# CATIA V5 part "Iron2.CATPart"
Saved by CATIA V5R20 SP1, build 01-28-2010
Part number: Part1
Bounding box of the stored display mesh (mm): x -79.132 to 79.133, y -300 to 0, z -3.105 to 127.728
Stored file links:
  J:\hosseini\Iron2.CATPart
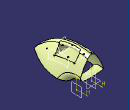
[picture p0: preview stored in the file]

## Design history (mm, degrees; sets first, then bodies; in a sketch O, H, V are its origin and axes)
Body1 (main body)
  Sketch1 on zx-plane, origin (0, 0, 0), H (-1, 0, 0), V (0, 0, 1)
    point P1 (70, 0)
    arc A1 centre (-241.0845, -75.0096) radius 320 from (70, 0) to (20.4309, 109.4076) ccw
    arc A2 centre (0, 95) radius 25 from (20.4309, 109.4076) to (-20.4309, 109.4076) ccw
    point P4 (0, 95)
    arc A3 centre (241.0845, -75.0096) radius 320 from (-20.4309, 109.4076) to (-70, 0) ccw
    point P7 (-70, 0)
    distance A2 H = 120
    distance P1 V = 70
    radius A2 = 25
    radius A1 = 320
    coincidence: P1 H, P7 H, P4 V
    tangency: A2 A1, A3 A2
    symmetry: A1 A3 V
  Sketch2 on yz-plane, origin (0, 0, 0), H (0, 1, 0), V (0, 0, 1)
    spline S1 through (0, 120) (-97.5385, 126.0039) (-300, 0)
    point P1 (0, 120)
    point P2 (-300, 0)
    distance P2 V = 300
    distance P1 H = 120
    coincidence: P1 V, P2 H
  Sketch3 on xy-plane, origin (0, 0, 0), H (1, 0, 0), V (0, 1, 0)
    spline S1 through (70, 0) (71.6167, -27.0715) (76.454, -63.6062) (62.9919, -184.814) (0, -300)
    reference projected point E1 (70, 0) from Sketch1.P7
    reference projected point E2 (0, -300) from Sketch2.P2
    point P1 (70, 0)
    point P2 (0, -300)
    coincidence: P1 H, P2 V, P1 E1, E2 P2
  Symmetry1: Reference yz-plane, ToTransfor Sketch3
  Sketch4 on xy-plane, origin (0, 0, 0), H (1, 0, 0), V (0, 1, 0)
    line L1 (0, 0) -> (0, -300.4665)
    vertical: L1 V
  Plane1: type Offset, RefPlane zx-plane, Offset -214
  Intersect1: ToIntersect1 Plane1, ToIntersect2 Sketch3
  Intersect2: ToIntersect1 Plane1, ToIntersect2 Sketch4
  Intersect3: ToIntersect1 Symmetry1, ToIntersect2 Plane1
  Intersect4: ToIntersect1 Sketch2, ToIntersect2 Plane1
  Sketch5 on Plane1, origin (0, -214, 0), H (-1, 0, 0), V (0, 0, 1)
    point P1 (-50.9944, 0)
    arc A1 centre (133.4907, -45.4446) radius 190 from (-50.9944, 0) to (-12.275, 76.4255) cw
    arc A2 centre (0, 66.1628) radius 16 from (-12.275, 76.4255) to (12.275, 76.4255) cw
    point P4 (0, 66.1628)
    arc A3 centre (-133.4907, -45.4446) radius 190 from (12.275, 76.4255) to (50.9944, 0) cw
    point P7 (50.9944, 0)
    reference projected point E1 (-50.9944, 0) from Intersect1
    reference projected point E2 (50.9944, 0) from Intersect3
    reference projected point E3 (0, 82.1628) from Intersect4
    radius A2 = 16
    radius A1 = 190
    tangency: A2 A1, A3 A2
    coincidence: P1 E1, E2 P7, P4 V, E3 A2
    symmetry: A3 A1 V
  Loft1: Sections (Sketch1; Sketch5), Guides (Sketch3; Sketch2; Symmetry1), SectionCouplingPoints ({coupling CouplingPoints (vertex [element of Sketch1 | element of Sketch1]; vertex [element of Sketch5 | element of Sketch5])}; {coupling CouplingPoints (vertex [element of Sketch1 | element of Sketch1]; vertex [element of Sketch5 | element of Sketch5])})
  Plane2: type Offset, RefPlane yz-plane, Offset 79
  Sketch6 on Plane2, origin (79, 0, 0), H (0, 1, 0), V (0, 0, 1)
    spline S1 through (0, 26.6689) (-20.4626, 28.402) (-45.2977, 19.9352) (-66.558, 0)
    reference projected line E1 (0, 0) -> (-300.4665, 0) from Sketch4
    point P1 (0, 26.6689)
    point P2 (-66.558, 0)
    coincidence: P1 V, P2 E1
  Symmetry2: Reference yz-plane, ToTransfor Sketch6
  Sketch7 on zx-plane, origin (0, 0, 0), H (-1, 0, 0), V (0, 0, 1)
    point P1 (79, 26.6689)
    arc A1 centre (0, 345.3941) radius 328.3698 from (79, 26.6689) to (-79, 26.6689) cw
    point P2 (0, 345.3941)
    point P3 (0, 17.0242)
    point P4 (-79, 26.6689)
    reference projected point E1 (79, 26.6689) from vertex of Symmetry2
    reference projected point E2 (-79, 26.6689) from Sketch6.P1
    coincidence: A1 P3, P3 V, E1 P1, P4 E2, P2 V
  Sweep1: type Unspec, Profile Sketch7, Guide (Sketch6; Symmetry2)
  Split1: ToCut Loft1, Cutting Sweep1
  Split2: ToCut Sweep1, Cutting Split1
  Join1: Elements (Split1; Split2)
  Fillet1: on edge [face of Sweep1 | face of Loft1]
  Sketch8 on Plane2, origin (79, 0, 0), H (0, 1, 0), V (0, 0, 1)
    spline S1 through (-43.5868, 124.1374) (-101.4249, 123.2792) (-153.9076, 109.9769)
  Project1: ToProject Sketch8, Support Fillet1, Direction (1, 0, 0)
  Symmetry3: Reference yz-plane, ToTransfor Sketch8
  Project2: ToProject Symmetry3, Support Fillet1, Direction (1, 0, 0)
  Sketch9 on yz-plane, origin (0, 0, 0), H (0, 1, 0), V (0, 0, 1)
    spline S1 through (-40.8756, 101.1965) (-93.9278, 105.1213) (-149.9943, 86.705)
  Plane3: type Normal, Curve Sketch9, RefPoint vertex of Sketch9
  Sketch10 on Plane3, origin (0, -77.6698, -43.232), H (1, 0, 0), V (0, -0.4863, 0.8738)
    circle A1 centre (0, 130.4913) radius 18.218
    point P1 (0, 130.4913)
    reference projected point E1 (0, 148.7093) from vertex of Sketch9
    coincidence: P1 V, A1 E1
  Sweep2: type Unspec, Profile Sketch10, Guide Sketch9
  Blend1: StartLimit {blendlimit Curve Project2, Support Fillet1}, EndLimit {blendlimit Curve Sketch9, Support Sweep2}
  Extrapol1: ToExtrapol edge of Blend1, Support Blend1, Length 10
  Symmetry4: Reference yz-plane, ToTransfor Extrapol1
  Sketch11 on Plane2, origin (79, 0, 0), H (0, 1, 0), V (0, 0, 1)
    spline S1 through (-43.5868, 124.1374) (-41.556, 103.6774) (-46.7523, 78.7066)
    reference projected point E1 (-43.5868, 124.1374) from vertex of Sketch8
    spline S2 through (-46.7523, 78.7066) (-99.3435, 76.8215) (-148.6547, 65.1341)
    spline S3 through (-148.6547, 65.1341) (-145.2669, 86.2469) (-153.9076, 109.9769)
    reference projected point E2 (-153.9076, 109.9769) from vertex of Sketch8
    point P1 (-43.5868, 124.1374)
    point P2 (-46.7523, 78.7066)
    point P3 (-148.6547, 65.1341)
    point P4 (-148.6547, 65.1341)
    point P5 (-153.9076, 109.9769)
    point P6 (-46.7523, 78.7066)
    coincidence: P1 E1, P3 P4, P5 E2, P2 P6
  Project3: ToProject Sketch11, Support Fillet1, Direction (1, 0, 0)
  Join2: Elements (Project3; Project1)
  Symmetry5: Reference yz-plane, ToTransfor Sketch11
  Project4: ToProject Symmetry5, Support Fillet1, Direction (1, 0, 0)
  Join3: Elements (Project4; Project2)
  Split3: ToCut Fillet1, Cutting (Join2; Join3)
  Point1: type Between, FirstPoint vertex [face of Loft1], SecondPoint vertex [face of Loft1], Ratio 0.5
  Point2: (0, 2, 2), relative to Point1
  Curve1: Elements (vertex [face of Loft1]; Point2; vertex [face of Loft1])
  Point3: type Between, FirstPoint vertex [face of Loft1], SecondPoint vertex [face of Loft1], Ratio 0.5
  Point4: (0, -2, 2), relative to Point3
  Curve2: Elements (vertex [face of Loft1]; Point4; vertex [face of Loft1])
  Join4: Elements (Extrapol1; Symmetry4)
  Boundary1: Boundary edge of Split3, BoundaryFrom vertex [face of Blend1], BoundaryTo vertex [face of Loft1]
  Boundary2: Boundary edge of Split3, BoundaryFrom vertex [face of Loft1], BoundaryTo vertex [face of Symmetry4]
  Loft2: Sections (Boundary1; Boundary2), Guides (Curve1; Curve2)
  Split4: ToCut Join4, Cutting Loft2
  Split5: ToCut Loft2, Cutting Split4
  Join5: Elements (Split3; Split4; Split5)
  Fillet2: radius 2, on edge [face of Loft2 | face of Symmetry4]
